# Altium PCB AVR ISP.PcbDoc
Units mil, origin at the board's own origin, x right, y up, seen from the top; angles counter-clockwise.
Board outline 3085 x 1730 mil, 2 copper layers (Top Layer, Bottom Layer); 43 components, 0 nets, 196 pads, 2 vias.
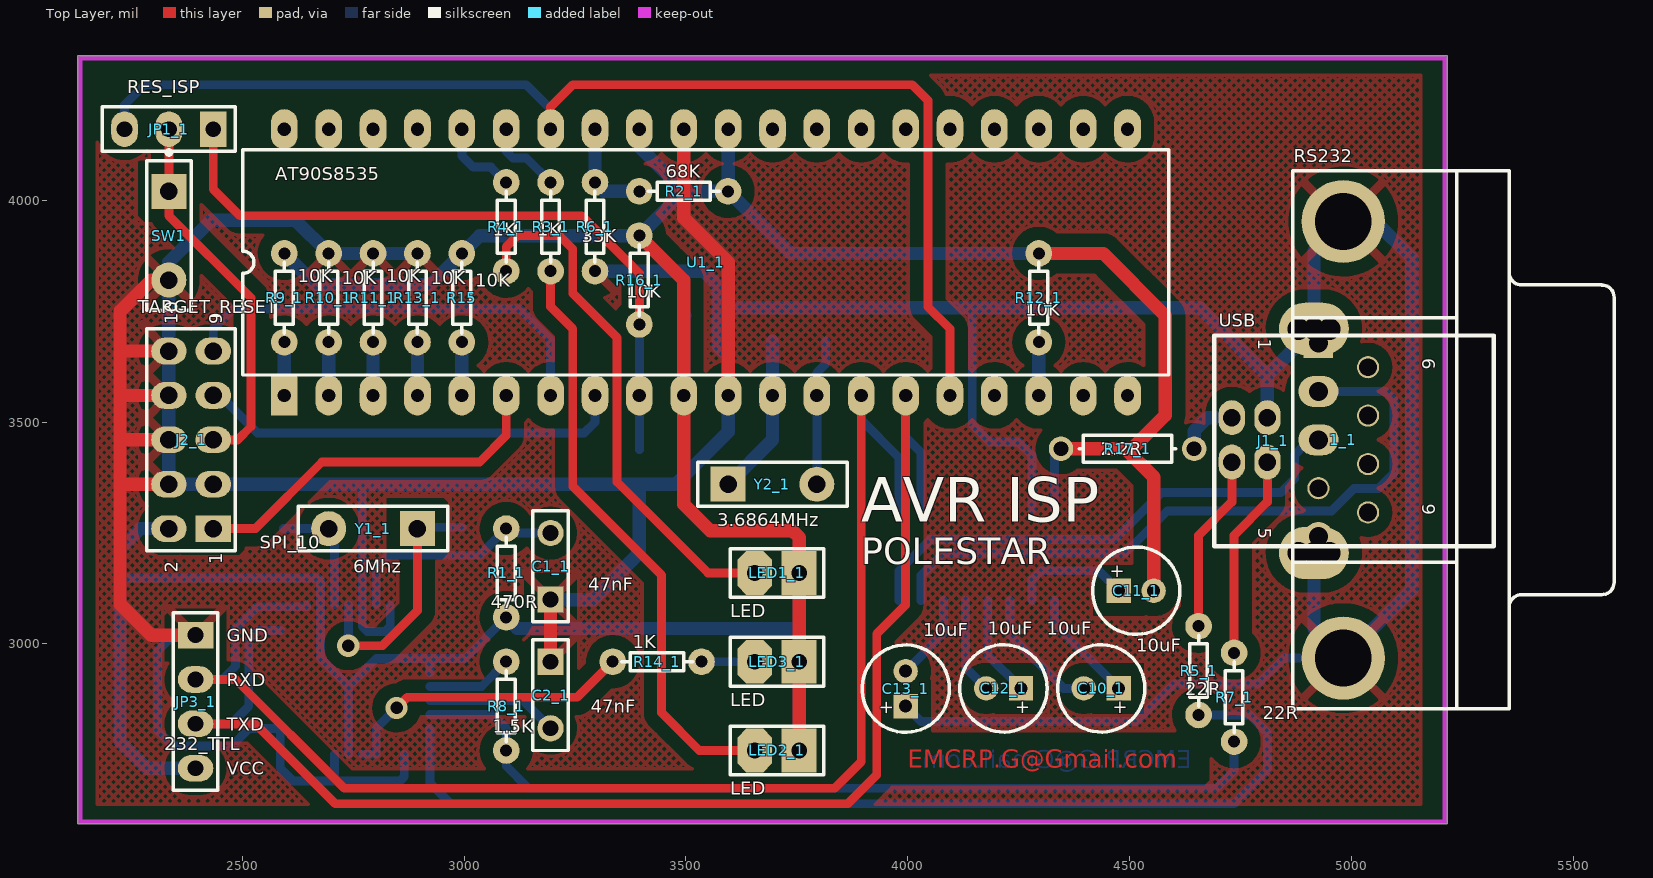
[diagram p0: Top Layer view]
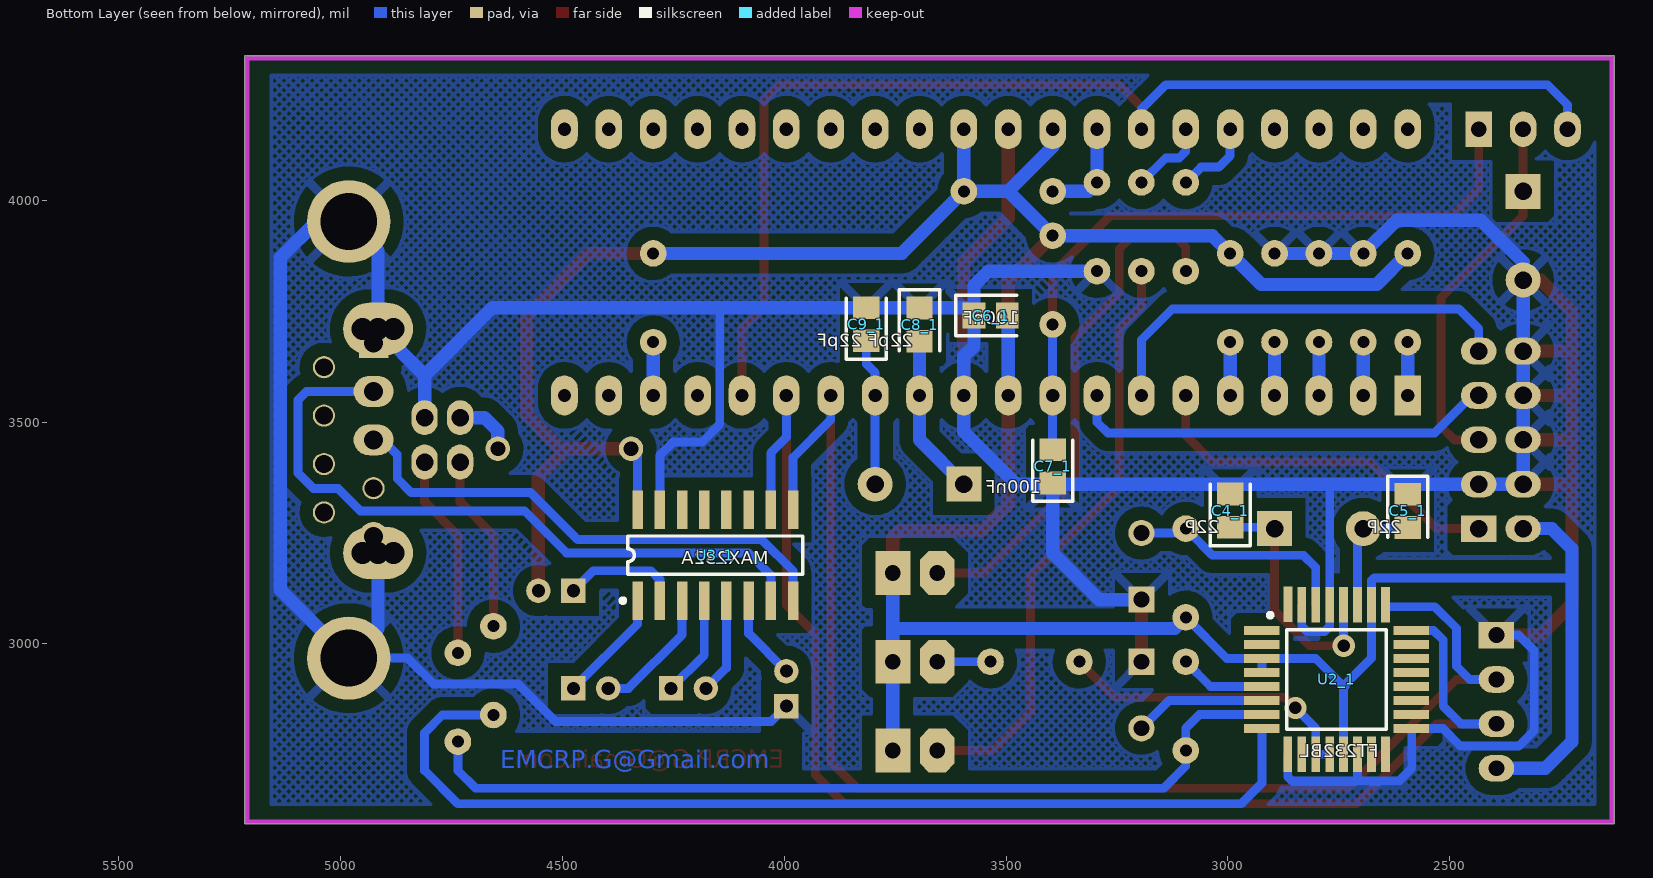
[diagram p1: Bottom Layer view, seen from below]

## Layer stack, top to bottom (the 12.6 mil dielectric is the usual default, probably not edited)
Top Layer: signal copper 1.4
Dielectric: dielectric 12.6, FR-4, Dk 4.8
Bottom Layer: signal copper 1.4

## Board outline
2130,2595 5215,2595 5215,4325 2130,4325

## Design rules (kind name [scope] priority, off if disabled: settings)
Clearance [All] p1: gap=10
PolygonConnect [All] p1: connectstyle=Relief reliefconductorwidth=10 reliefentries=4 polygonreliefangle="90 Angle" airgapwidth=10
RoutingVias [All] p1: holewidth=28 width=50 viastyle="Through Hole" minholewidth=28 minwidth=50 maxholewidth=28 maxwidth=50
SilkscreenOverComponentPads [All] p1: minsilkscreentomaskgap=10
SolderMaskExpansion [All] p1: expansion=4
Width [All] p1: maxlimit=10 minlimit=10 preferedwidth=10
27 further rules are at their usual default settings.

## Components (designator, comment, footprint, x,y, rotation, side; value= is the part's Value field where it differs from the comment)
1_1 "RS232" DSUB1.385-2H9 5355,3460 r270 top
C1_1 "47nF" CAP_M_X2 3195,3200 r90 top
C2_1 "47nF" CAP_M_X2 3195,2860 r270 top
C4_1 "22P" CC2012-0805 2995,3300 r90 bottom
C5_1 "22P" CC2012-0805 2595,3300 r270 bottom
C6_1 "100nF" CC2012-0805 3535,3740 r180 bottom
C7_1 "100nF" CC2012-0805 3395,3400 r90 bottom
C8_1 "22pF" CC2012-0805 3695,3720 r270 bottom
C9_1 "22pF" CC2012-0805 3815,3720 r90 bottom
C10_1 "10uF" CAP_POL1 4475,2900 r180 top
C11_1 "10uF" CAP_POL1 4475,3120 r0 top
C12_1 "10uF" CAP_POL1 4255,2900 r180 top
C13_1 "10uF" CAP_POL1 3995,2860 r90 top
J1_1 "USB" USB_B 5215,3520 r180 top
J2_1 "SPI_10" HDR2X5 2435,3260 r90 top
JP1_1 "RES_ISP" HDR1X3 2435,4160 r180 top
JP3_1 "232_TTL" HDR1X4 2395,3020 r270 top
LED1_1 "LED" LED 3755,3160 r180 top
LED2_1 "LED" LED 3755,2760 r180 top
LED3_1 "LED" LED 3755,2960 r180 top
R1_1 "470R" AXIAL-0.2 3095,3160 r270 top
R2_1 "68K" AXIAL-0.2 3495,4020 r0 top
R3_1 "1K" AXIAL-0.2 3195,3940 r270 top
R4_1 "1K" AXIAL-0.2 3095,3940 r270 top
R5_1 "22R" AXIAL-0.2 4655,2940 r270 top
R6_1 "33K" AXIAL-0.2 3295,3940 r90 top
R7_1 "22R" AXIAL-0.2 4735,2880 r270 top
R8_1 "1.5K" AXIAL-0.2 3095,2860 r90 top
R9_1 "10K" AXIAL-0.2 2595,3780 r270 top
R10_1 "10K" AXIAL-0.2 2695,3780 r270 top
R11_1 "10K" AXIAL-0.2 2795,3780 r270 top
R12_1 "10K" AXIAL-0.2 4295,3780 r270 top
R13_1 "10K" AXIAL-0.2 2895,3780 r270 top
R14_1 "1K" AXIAL-0.2 3435,2960 r180 top
R15 "10K" AXIAL-0.2 2995,3780 r270 top
R16_1 "10K" AXIAL-0.2 3395,3820 r270 top
R17_1 "2.2R" AXIAL-0.3 4495,3440 r180 top
SW1 "TARGET_RESET" SPST-2 2335,3920 r270 top
U1_1 "AT90S8535" DIP40 3695,4260 r0 top
U2_1 "FT232BL" 32A 2755,2920 r180 bottom
U3_1 "MAX232A" NSO16 4155,3200 r180 bottom
Y1_1 "6Mhz" SPST-2 2795,3260 r180 top
Y2_1 "3.6864MHz" SPST-2 3695,3360 r0 top

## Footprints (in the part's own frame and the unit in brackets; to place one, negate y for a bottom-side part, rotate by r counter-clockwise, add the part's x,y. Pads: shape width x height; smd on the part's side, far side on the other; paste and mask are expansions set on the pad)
32A [mil]
  rect 80x20 smd: 1(-168.46,110.24) 2(-168.46,78.74) 3(-168.46,47.24) 4(-168.46,15.75) 5(-168.46,-15.75) 6(-168.46,-47.24) 7(-168.46,-78.74) 8(-168.46,-110.24) 17(168.47,-110.24) 18(168.46,-78.74) 19(168.46,-47.24) 20(168.46,-15.75) 21(168.46,15.75) 22(168.46,47.24) 23(168.46,78.74) 24(168.47,110.24)
  rect 20x80 smd: 9(-110.24,-168.46) 10(-78.74,-168.46) 11(-47.24,-168.46) 12(-15.75,-168.46) 13(15.75,-168.46) 14(47.24,-168.46) 15(78.74,-168.46) 16(110.24,-168.46) 25(110.24,168.47) 26(78.74,168.47) 27(47.24,168.47) 28(15.75,168.47) 29(-15.75,168.47) 30(-47.24,168.47) 31(-78.74,168.47) 32(-110,170)
  silkscreen extent -155,-112 112,150
AXIAL-0.2 [mil]
  round 60 hole 27: 1(-100,0) 2(100,0)
  silkscreen extent -80,-20 80,20
AXIAL-0.3 [mm]
  round 1.4 hole 0.85: 1(-3.81,0) 2(3.81,0)
  silkscreen extent -2.77,-0.76 2.77,0.76
CAP_M_X2 [mm]
  rect 1.5x1.5 hole 0.9: 1(-2.54,0)
  round 1.5 hole 0.9: 2(1.27,0)
  silkscreen extent -3.81,-1.02 2.54,1.02
CAP_POL1 [mil]
  rect 55x55 hole 29.53: 1(0,0)
  round 55 hole 29.53: 2(78.74,0)
  silkscreen extent -59,-98 138,98
CC2012-0805 [mm]
  rect 1.3x1.5 smd: 1(-0.942,0) 2(0.958,0)
  silkscreen extent -1.99,-1.15 1.51,1.15
DIP40 [mil]
  rect 60x90 hole 30: 1(-1100,-700)
  oval 60x90 hole 30: 2(-1000,-700) 3(-900,-700) 4(-800,-700) 5(-700,-700) 6(-600,-700) 7(-500,-700) 8(-400,-700) 9(-300,-700) 10(-200,-700) 11(-100,-700) 12(0,-700) 13(100,-700) 14(200,-700) 15(300,-700) 16(400,-700) 17(500,-700) 18(600,-700) 19(700,-700) 20(800,-700) 21(800,-100) 22(700,-100) 23(600,-100) 24(500,-100) 25(400,-100) 26(300,-100) 27(200,-100) 28(100,-100) 29(0,-100) 30(-100,-100) 31(-200,-100) 32(-300,-100) 33(-400,-100) 34(-500,-100) 35(-600,-100) 36(-700,-100) 37(-800,-100) 38(-900,-100) 39(-1000,-100) 40(-1100,-100)
  silkscreen extent -1193,-654 893,-146
DSUB1.385-2H9 [mm]
  rect 1.69x1.69 hole 1.09: 1(-5.54,-10.92)
  oval 1.778x2.286 hole 1.09: 2(-2.77,-10.92) 3(0,-10.92)
  round 1.27 hole 1.016: 4(2.77,-10.92) 6(-4.155,-8.08) 7(-1.385,-8.08) 8(1.385,-8.08) 9(4.155,-8.08)
  round 1.69 hole 1.09: 5(5.54,-10.92)
  round 4.76 hole 3.26: 10(-12.495,-9.5) 11(12.495,-9.5)
  silkscreen extent -15.4,-12.4 15.4,6
HDR1X3 [mil]
  rect 60x80 hole 35.43: 1(0,0)
  oval 60x80 hole 35.43: 2(100,0) 3(200,0)
  silkscreen extent -50,-50 250,50
HDR1X4 [mil]
  rect 60x80 hole 35.43: 1(0,0)
  oval 60x80 hole 35.43: 2(100,0) 3(200,0) 4(300,0)
  silkscreen extent -50,-50 350,50
HDR2X5 [mil]
  rect 60x80 hole 39.37: 1(0,0)
  oval 60x80 hole 39.37: 2(0,100) 3(100,0) 4(100,100) 5(200,0) 6(200,100) 7(300,0) 8(300,100) 9(400,0) 10(400,100)
  silkscreen extent -50,-50 450,150
LED [mm]
  rect 2x2.5 hole 0.9: 1(0,0)
  oct 2x2.5 hole 0.9: 2(2.54,0)
  silkscreen extent -1.4,-1.4 3.94,1.4
NSO16 [mm]
  rect 0.6x2.2 smd: 1(-4.445,-2.6) 2(-3.175,-2.6) 3(-1.905,-2.6) 4(-0.635,-2.6) 5(0.635,-2.6) 6(1.905,-2.6) 7(3.175,-2.6) 8(4.445,-2.6) 9(4.445,2.6) 10(3.175,2.6) 11(1.905,2.6) 12(0.635,2.6) 13(-0.635,2.6) 14(-1.905,2.6) 15(-3.175,2.6) 16(-4.445,2.6)
  silkscreen extent -5.42,-2.72 5,1.1
SPST-2 [mm]
  rect 2x2 hole 1: 1(-2.54,0)
  round 2 hole 1: 2(2.54,0)
  silkscreen extent -4.89,-1.27 4.28,1.27
USB_B [mm]
  oval 1.5x2 hole 1: 1(12.319,0.254) 2(12.319,2.794) 3(10.287,2.794) 4(10.287,0.254)
  oval 4x3 hole 1.27: 5(7.62,8.001) 6(7.62,-4.826)
  silkscreen extent -2.67,-4.44 13.33,7.62

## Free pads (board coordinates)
  round 50 hole 50: 1(4880,3205) 2(4950,3205) 3(4880,3710) 4(4950,3710)

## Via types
v1: diameter 50, hole 28, Top Layer to Bottom Layer, 2 vias

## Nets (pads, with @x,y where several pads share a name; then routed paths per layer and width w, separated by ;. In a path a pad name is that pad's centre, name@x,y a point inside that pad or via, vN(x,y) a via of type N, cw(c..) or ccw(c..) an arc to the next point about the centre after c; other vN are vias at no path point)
pads on no net: 1_1.1 1_1.2 1_1.3 1_1.4 1_1.5 1_1.6 1_1.7 1_1.8 1_1.9 1_1.10 1_1.11 C1_1.1 C1_1.2 C2_1.1 C2_1.2 C4_1.1 C4_1.2 C5_1.1 C5_1.2 C6_1.1 C6_1.2 C7_1.1 C7_1.2 C8_1.1 C8_1.2 C9_1.1 C9_1.2 C10_1.1 C10_1.2 C11_1.1 C11_1.2 C12_1.1 C12_1.2 C13_1.1 C13_1.2 J1_1.1 J1_1.2 J1_1.3 J1_1.4 J1_1.5 J1_1.6 J2_1.1 J2_1.2 J2_1.3 J2_1.4 J2_1.5 J2_1.6 J2_1.7 J2_1.8 J2_1.9 J2_1.10 JP1_1.1 JP1_1.2 JP1_1.3 JP3_1.1 JP3_1.2 JP3_1.3 JP3_1.4 LED1_1.1 LED1_1.2 LED2_1.1 LED2_1.2 LED3_1.1 LED3_1.2 R1_1.1 R1_1.2 R2_1.1 R2_1.2 R3_1.1 R3_1.2 R4_1.1 R4_1.2 R5_1.1 R5_1.2 R6_1.1 R6_1.2 R7_1.1 R7_1.2 R8_1.1 R8_1.2 R9_1.1 R9_1.2 R10_1.1 R10_1.2 R11_1.1 R11_1.2 R12_1.1 R12_1.2 R13_1.1 R13_1.2 R14_1.1 R14_1.2 R15.1 R15.2 R16_1.1 R16_1.2 R17_1.1 R17_1.2 SW1.1 SW1.2 U1_1.1 U1_1.2 U1_1.3 U1_1.4 U1_1.5 U1_1.6 U1_1.7 U1_1.8 U1_1.9 U1_1.10 U1_1.11 U1_1.12 U1_1.13 U1_1.14 U1_1.15 U1_1.16 U1_1.17 U1_1.18 U1_1.19 U1_1.20 U1_1.21 U1_1.22 U1_1.23 U1_1.24 U1_1.25 U1_1.26 U1_1.27 U1_1.28 U1_1.29 U1_1.30 U1_1.31 U1_1.32 U1_1.33 U1_1.34 U1_1.35 U1_1.36 U1_1.37 U1_1.38 U1_1.39 U1_1.40 U2_1.1 U2_1.2 U2_1.3 U2_1.4 U2_1.5 U2_1.6 U2_1.7 U2_1.8 U2_1.9 U2_1.10 U2_1.11 U2_1.12 U2_1.13 U2_1.14 U2_1.15 U2_1.16 U2_1.17 U2_1.18 U2_1.19 U2_1.20 U2_1.21 U2_1.22 U2_1.23 U2_1.24 U2_1.25 U2_1.26 U2_1.27 U2_1.28 U2_1.29 U2_1.30 U2_1.31 U2_1.32 U3_1.1 U3_1.2 U3_1.3 U3_1.4 U3_1.5 U3_1.6 U3_1.7 U3_1.8 U3_1.9 U3_1.10 U3_1.11 U3_1.12 U3_1.13 U3_1.14 U3_1.15 U3_1.16 Y1_1.1 Y1_1.2 Y2_1.1 Y2_1.2
copper on no net: | length 51122
  Top Layer w20: 2335,4160 2335,3965 2520,3780 2520,3490 2490,3460 2435,3460 ; 2395,2820 2530,2820 2710,2640 3865,2640 3930,2705 3930,3023 3995,3088 3995,3560 ; 2395,2920 2485,2920 2730,2675 3835,2675 3895,2735 3895,3560 ; 2435,3260 2530,3260 2680,3410 3035,3410 3095,3470 3095,3560 ; 2435,4160 2435,4025 2495,3965 3265,3965 3395,3835 3395,3720 ; v1(2739.25,2996) 2816,2996 2895,3075 2895,3260 ; v1(2848,2856) 2872,2880 3255,2880 3335,2960 ; 3095,3840 3095,3895 3120,3920 3215,3920 3245,3890 3245,3790 3345,3690 3345,3365 3550,3160 3655,3160 ; 3195,3560 3195,3570 ; 3195,3840 3195,3760 3245,3710 3245,3355 3445,3155 3445,2845 3530,2760 3655,2760 ; 3195,4160 3195,4210 3245,4260 4010,4260 4045,4225 4045,3760 4095,3710 4095,3560 ; 4655,3040 4655,3245 4730,3320 4730,3410 ; 4735,2980 4735,3245 4810,3320 4810,3410
  Top Layer w30: 2225,3360 2335,3360 ; 2225,3460 2335,3460 ; 2225,3560 2335,3560 ; 2225,3660 2335,3660 ; 2355,3020 2295,3020 2225,3090 2225,3750 2295,3820 2355,3820 ; 3195,2960 3195,3100 ; 3395,3920 3495,3820 3495,3315 3555,3255 3740,3255 3755,3240 3755,2760 ; 3495,4160 3495,3960 3595,3860 3595,3560 ; 4295,3880 4440,3880 4580,3740 4580,3515 4505,3440 4345,3440 ; 4490,3440 4553.74,3376.26 4553.74,3120
  Bottom Layer w20: 2225,3149 2670,3149 2676.26,3142.74 2676.26,2968.74 2740,2905 2802.24,2967.24 3002.24,2967.24 3095,3060 ; 2235,4160 2235,4215 2280,4260 3140,4260 3195,4205 3195,4160 ; 2395,2820 2475,2820 2515,2860 2515,3009 2536.24,3030.24 2586.53,3030.24 ; 2395,2920 2455,2920 2485,2950 2485,3035 2534,3084 2644.76,3084 2644.76,3088.47 ; 2395,3020 2345,3020 2310,2985 2310,2805 2345,2770 2476,2770 2515.76,2809.76 2586.53,2809.76 ; 2435,3660 2435,3710 2480,3755 3125,3755 3195,3685 3195,3560 ; 2450,3560 2535,3475 3270,3475 3295,3500 3295,3560 ; 2586,2809.76 2586,2720 2615,2691 2855,2691 2865.24,2701.24 2865.24,2751.54 ; 2592.72,3260 2695,3260 ; 2677.28,3277.72 2707.76,3247.24 2707.76,3088.47 ; 2707.76,2691 2707.76,2751.54 ; 2736.26,2903.74 2739.25,2900.75 2739.25,2751.54 ; v1(2739.25,2996) 2739.25,3088.47 ; 2770.75,2751.54 2802.24,2751.54 2802.24,2810.24 v1(2848,2856) ; 2770.75,3360 2770.75,3040 2782.75,3028 2821.74,3028 2833.74,3040 2833.74,3088.47 ; 2802.24,3088.47 2802.24,3172.24 2830,3200 3035,3200 3085,3250 3195,3250 ; 2895,3260 2897.91,3262.91 2995,3262.91 ; 2923.46,2809.76 2923,2809.76 2923,2687 2970,2640 4735,2640 4810,2715 4810,2800 4770,2840 4655,2840 ; 2923.46,2841.26 3063.74,2841.26 3095,2810 3095,2725 3145,2675 4695,2675 4735,2715 4735,2780 ; 2923.46,2872.76 3132.24,2872.76 3195,2810 ; 2923.46,2904.25 3039.25,2904.25 3095,2960 ; 2923.46,2935.75 2923.46,2967.24 ; 2995,4160 2995,4100 3020.64,4074.36 3060.64,4074.36 3095,4040 ; 3095,4160 3095,4110 3110,4095 3140,4095 3195,4040 ; 3395,3437.72 3395,3560 3395,3721 ; 3535,2960 3655,2960 ; 3795,3360 3795,3560 3795,3611 3815,3631 3815,3682.91 ; 3895,3560 3895,3505 3980,3420 3980,3302.36 ; 3980,3097.64 3980,3165 4050,3235 4465,3235 4571,3341 4840,3341 4871.81,3372.81 4871.81,3426.81 4905,3460 4925.08,3460 ; 3995,2860 4030,2825 4515,2825 4600,2910 4790,2910 4848.07,2968.07 4980.98,2968.07 ; 3995,2938.74 4080,3023.74 4080,3097.64 ; 3995,3560 3995,3466 4030,3431 4030,3302.36 ; 4030,3097.64 4030,3155 4080,3205 4490,3205 4585,3300 4955,3300 5005,3350 5060,3350 5095,3385 5095,3550 5075.94,3569.06 4925.08,3569.06 ; 4130,3097.64 4130,2946.26 4176.26,2900 ; 4145,3757.72 4145,3494.95 4185,3454.95 4250.05,3454.95 4280,3425 4280,3302.36 ; 4180,3097.64 4180,2975 4255,2900 ; 4230,3097.64 4230,3021 4351,2900 4396.26,2900 ; 4280,3097.64 4280,3145 4300,3165 4430,3165 4475,3120 ; 4330,3097.64 4330,3045 4475,2900 ; 4330,3302.36 4330,3425 4345,3440
  Bottom Layer w30: 2335,3260 2270,3260 2225,3215 2225,2780 2285,2720 2355,2720 ; 2595,3560 2595,3680 ; 2595,3880 2665,3810 2925,3810 3035,3920 3395,3920 3495,4020 ; 2695,3560 2695,3680 ; 2795,3560 2795,3680 ; 2895,3560 2895,3680 ; 2895,3880 2695,3880 2620,3955 2430,3955 2335,3860 2335,3360 3475,3360 3477.91,3362.91 ; 2995,3560 2995,3680 ; 3095,3060 3120,3035 3755,3035 ; 3195,3100 3290,3100 3395,3205 3395,3360 ; 3295,3840 3540,3840 3572.09,3807.91 3572.09,3671.22 3595,3648.31 3595,3478 3479.91,3362.91 ; 3295,4160 3295,4040 3315,4020 3395,4020 ; 3395,4160 3395,4120 3495,4020 ; 3495,3560 3495,3737.72 3497.28,3740 ; 3572.09,3740 3589.8,3757.72 4657.28,3757.72 4810,3605 ; 3595,3360 3695,3460 3695,3682.28 ; 3595,4011 3595,4160 ; 3755,2765 3755,3160 ; 4295,3560 4295,3680 ; 4295,3880 3735,3880 3595,4020 3495,4020 ; 4645,3440 4645,3480 4675,3510 4730,3510 ; 4810,3510 4810,3605 ; 4915,3205 4915,3034.05 4980.98,2968.07 5135,3122.09 5135,3870 5053.07,3951.93 ; 4980.98,3951.93 4915,3885.95 4915,3710 4810,3605

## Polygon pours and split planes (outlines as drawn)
no net on Top Layer "Top Layer-No Net" (hatched 90Degree grid 15 track 8, remove dead copper, pour order 2): 0,0
no net on Bottom Layer "Bottom Layer-No Net" (hatched 90Degree grid 15 track 8, remove dead copper, pour order 4): 0,0

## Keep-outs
Keep-Out Layer:
  lines w10: 2135,2600 5210,2600 5210,4320 2135,4320 2135,2600

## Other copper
Top Layer:
  text "EMCRP.G@Gmail.com" at 4000,2721 h40
Bottom Layer:
  text "EMCRP.G@Gmail.com" at 4640,2720 h40

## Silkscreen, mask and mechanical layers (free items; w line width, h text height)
Top Overlay:
  text "AVR ISP" at 3895,3275 h100
  text "POLESTAR" at 3895,3180 h60
  text "GND" at 2465,3005 h30
  text "RXD" at 2465,2905 h30
  text "TXD" at 2465,2805 h30
  text "VCC" at 2465,2705 h30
